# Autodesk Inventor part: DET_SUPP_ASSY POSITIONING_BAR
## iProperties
Shininess: 64.0
Length Units: 11272
Angle Units: 11279
Time Units: 11290
Mass Units: 11286
Length Display Precision: 3
Angle Display Precision: 2
Compacted: True
Part Number: DET_SUPP_ASSY POSITIONING_BAR
Document SubType Name: Modeling
Created: 2004-08
Designer: John Blackburn
Manufacturer: Standard
Standards Organization: Custom
Material: Aluminum-6061
Density: 0.0
Volumn: 0.0
Area: 0.0
PropertySet Name: Model Information
Control State: 0
Master: False
Checked Out: False
Author: John Blackburn
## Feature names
1. ExtrusionMidplane1
2. AM_HOLE_0301DE_1 [Hole]
3. AM_HOLE_0301DE_2 [Hole]
